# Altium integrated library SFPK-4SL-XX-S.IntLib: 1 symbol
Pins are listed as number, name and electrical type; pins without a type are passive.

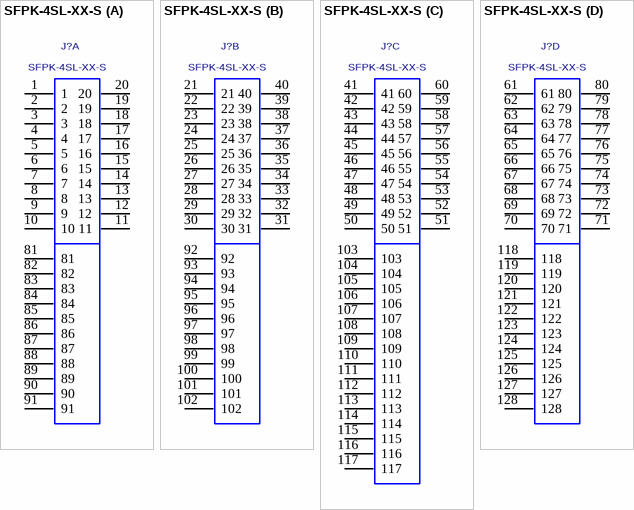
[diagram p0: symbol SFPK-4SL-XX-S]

## SFPK-4SL-XX-S
designator J?
SFPK-SL; MANUFACTURER: SAMTEC
footprint SFPK-4SL-XX-S
part A pins: 1, 2, 3, 4, 5, 6, 7, 8, 9, 10, 11, 12, 13, 14, 15, 16, 17, 18, 19, 20, 81, 82, 83, 84, 85, 86, 87, 88, 89, 90, 91
part B pins: 21, 22, 23, 24, 25, 26, 27, 28, 29, 30, 31, 32, 33, 34, 35, 36, 37, 38, 39, 40, 92, 93, 94, 95, 96, 97, 98, 99, 100, 101, 102
part C pins: 41, 42, 43, 44, 45, 46, 47, 48, 49, 50, 51, 52, 53, 54, 55, 56, 57, 58, 59, 60, 103, 104, 105, 106, 107, 108, 109, 110, 111, 112, 113, 114, 115, 116, 117
part D pins: 61, 62, 63, 64, 65, 66, 67, 68, 69, 70, 71, 72, 73, 74, 75, 76, 77, 78, 79, 80, 118, 119, 120, 121, 122, 123, 124, 125, 126, 127, 128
